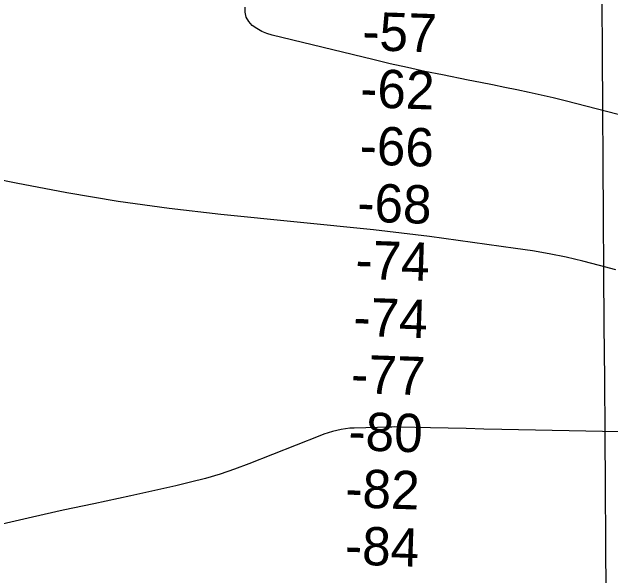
# Model space of a CAD drawing. Extents: x 3508733 to 3546731, y 546897 to 572481.
# Drawn here: x 3532902 to 3533948, y 562985 to 563970 of the extents above; entities that cross this region are included whole.
import ezdxf

# ---------------------------------------------------------------- set-up
doc = ezdxf.new("R2010")
doc.units = 0
for name, color, linetype in [('V-GRID-MAJR', 7, 'Continuous'), ('V-RIVR-RANG', 7, 'Continuous'), ('V-TOPO-MINR', 7, 'Continuous')]:
    doc.layers.add(name, color=color, linetype=linetype)

msp = doc.modelspace()

# ---------------------------------------------------------------- linework, layer by layer
at = {"layer": 'V-GRID-MAJR'}
msp.add_spline([(3534014.4590000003, 552440.283), (3533972.165, 558498.1140000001), (3533929.85, 564559.029), (3533887.535, 570619.961), (3533887.514, 570623.028)], degree=3, dxfattribs=at)
at = {"layer": 'V-TOPO-MINR'}
for points in [[(3534016.3133283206, 563776.7576145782), (3533869.6595472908, 563814.4198477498), (3533848.6084616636, 563819.6604072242), (3533827.5093154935, 563824.6926465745), (3533806.3380785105, 563829.4124057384), (3533785.1187809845, 563833.9238447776), (3533763.859147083, 563838.2577530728), (3533742.5938162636, 563842.563379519), (3533721.319940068, 563846.8265831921), (3533700.040366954, 563851.0615050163), (3533654.8426761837, 563860.009604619), (3533624.3277847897, 563866.2512944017), (3533593.8692007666, 563872.7489988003), (3533563.4950778, 563879.6307251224), (3533533.177262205, 563886.7684660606), (3533357.251818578, 563929.3606399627), (3533347.8393360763, 563932.307373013), (3533338.801493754, 563936.0195110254), (3533330.325611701, 563940.8797564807), (3533322.224369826, 563946.505406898), (3533316.0613648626, 563953.3669869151), (3533311.6366526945, 563960.903164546), (3533309.81937972, 563969.4512385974), (3533309.7403995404, 563978.6739102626)], [(3533958.095870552, 563519.0242739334), (3533929.199346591, 563526.9229813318), (3533900.1710326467, 563534.3613230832), (3533870.9573797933, 563540.9983701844), (3533841.628828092, 563547.0293440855), (3533812.127928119, 563552.1512081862), (3533782.5121292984, 563556.6669990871), (3533632.3108919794, 563577.199227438), (3533607.8800274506, 563580.4090060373), (3533583.4288899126, 563583.4484330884), (3533558.947342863, 563586.2323328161), (3533534.4455228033, 563588.8458809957), (3533267.3030593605, 563615.9311363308), (3533177.3342021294, 563626.4273542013), (3533087.639981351, 563638.724378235), (3532998.3577152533, 563653.7226115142), (3532909.3500856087, 563670.5216509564), (3532762.5476229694, 563700.5305963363)], [(3534610.909096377, 563223.2659425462), (3533758.4043354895, 563240.1362812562), (3533727.237191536, 563240.7751770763), (3533696.0707008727, 563241.443559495), (3533664.905190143, 563242.1561718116), (3533633.7403327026, 563242.8982707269), (3533581.0314695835, 563244.1907997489), (3533576.2215892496, 563244.2712131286), (3533571.4117829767, 563244.3016065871), (3533566.6020877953, 563244.2569701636), (3533561.7924666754, 563244.1623138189), (3533500.654756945, 563242.4819246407), (3533492.9155190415, 563242.0270723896), (3533485.218400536, 563241.2534188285), (3533477.584461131, 563240.001563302), (3533469.992641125, 563238.4309064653), (3533462.4827068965, 563236.4608090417), (3533455.0391744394, 563234.2806889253), (3533447.695244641, 563231.7855347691), (3533440.4177166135, 563229.0803579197), (3533316.3364442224, 563179.9225446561), (3533291.2847119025, 563170.5969133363), (3533266.008306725, 563161.9780331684), (3533240.394892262, 563154.4192797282), (3533214.556804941, 563147.5672774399), (3533188.522475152, 563141.3667126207), (3533162.4520724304, 563135.3251059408), (3533136.327560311, 563129.5219364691), (3533110.1669752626, 563123.8777251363), (3533045.2525138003, 563110.1823190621), (3532991.730161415, 563098.6088495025), (3532938.2896354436, 563086.6773615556), (3532884.971849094, 563074.2088460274)]]:
    msp.add_lwpolyline(points, dxfattribs=at)

# ---------------------------------------------------------------- texts
at = {"layer": 'V-RIVR-RANG'}
for s, p in [('-57', (3533514.14822098, 563903.5563271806)), ('-62', (3533510.3433902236, 563803.6276576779)), ('-66', (3533509.426743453, 563703.6034477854)), ('-68', (3533505.3454728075, 563603.6838897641)), ('-74', (3533502.0561081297, 563503.7391687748)), ('-74', (3533498.5031081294, 563403.8021687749)), ('-77', (3533494.4100329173, 563303.8830012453)), ('-80', (3533489.814296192, 563203.9804947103)), ('-82', (3533484.4158489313, 563104.1045416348)), ('-84', (3533483.761837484, 563004.0716107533))]:
    msp.add_text(s, height=67.00000000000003, rotation=358.1053611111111, dxfattribs=at).set_placement(p)

doc.saveas('drawing.dxf')
